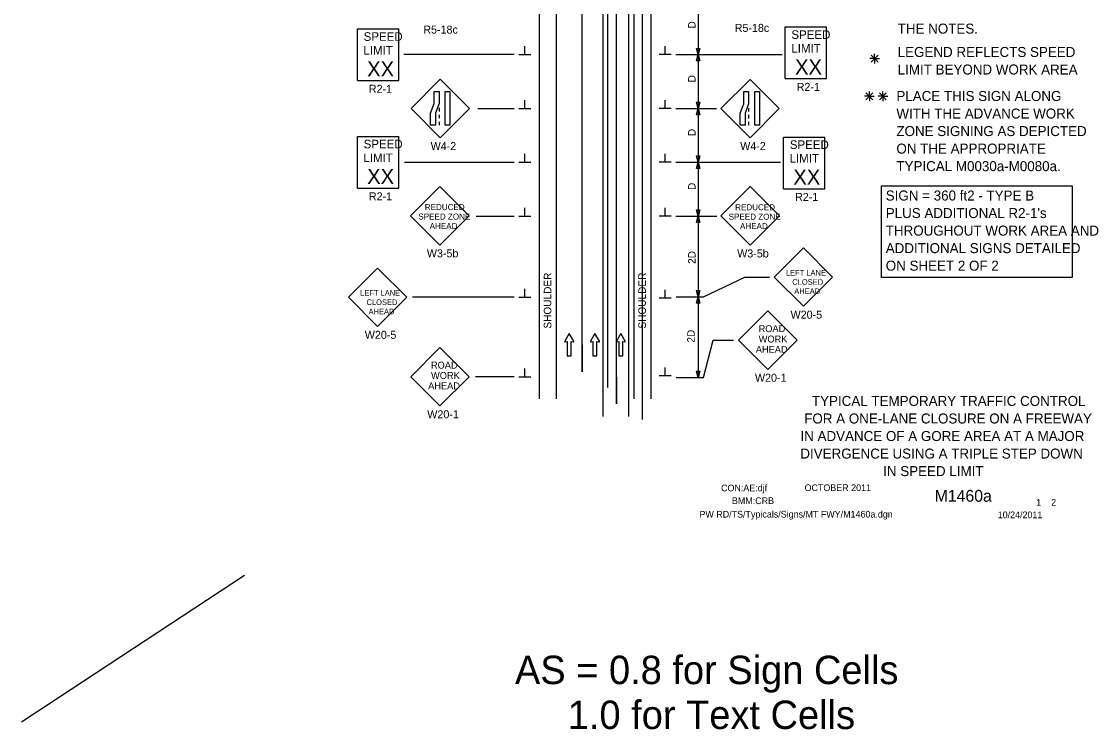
# Model space of a CAD drawing. Extents: x 16440 to 18464, y 5737 to 6974.
# Drawn here: x 16440 to 17442, y 5737 to 6395 of the extents above; entities that cross this region are included whole.
import ezdxf

# ---------------------------------------------------------------- set-up
doc = ezdxf.new("R2010")
doc.units = 0
for name, color, linetype in [('ALI_LEGAL_EX', 7, 'Continuous'), ('BORDER', 7, 'Continuous'), ('BORDER_SIGNAL_WO', 7, 'Continuous'), ('MT_SCRATCH_LEVEL_E', 7, 'Continuous'), ('PAVT_EDGE_EX', 7, 'Continuous'), ('TRAFFIC_SIGNS_PR', 7, 'Continuous'), ('TYPICAL_TEXT_DIMEN_EX', 7, 'Continuous'), ('TYPICAL_TEXT_DIMEN_PR', 7, 'Continuous')]:
    doc.layers.add(name, color=color, linetype=linetype)

msp = doc.modelspace()

# ---------------------------------------------------------------- linework, layer by layer
at = {"layer": 'ALI_LEGAL_EX'}
for p, q in [((16980.7, 6974.1), (16980.7, 6156)), ((17004.7, 6974.1), (17004.7, 6156)), ((16980.7, 6891.5), (16980.7, 6027.6)), ((17004.7, 6891.5), (17004.7, 6027.6)), ((16961.5, 6069.2), (16961.5, 6569.5)), ((16985.5, 6054.7), (16985.5, 6555)), ((16993.6, 6039.3), (16993.6, 6539.6)), ((17017.6, 6024.8), (17017.6, 6525.1))]:
    msp.add_line(p, q, dxfattribs=at)
for points in [[(16961.5, 6369.2), (16961.5, 6394.2)], [(16985.5, 6369.2), (16985.5, 6394.2)], [(16961.5, 6269.2), (16961.5, 6294.2)], [(16985.5, 6269.2), (16985.5, 6294.2)], [(16961.5, 6169.2), (16961.5, 6194.2)], [(16985.5, 6169.2), (16985.5, 6194.2)], [(16961.5, 6094.2), (16961.5, 6069.2)], [(16961.5, 6069.2), (16961.5, 6094.2)], [(16985.5, 6069.2), (16985.5, 6094.2)], [(16993.6, 6064.3), (16993.6, 6039.3)]]:
    msp.add_lwpolyline(points, dxfattribs=at)
at = {"layer": 'MT_SCRATCH_LEVEL_E'}
for p, q in [((16949.5, 6104.8), (16945.4, 6097.6)), ((16945.9, 6096.9), (16947.7, 6097.2)), ((16947.7, 6097.2), (16947.7, 6083.9)), ((16953.7, 6097.6), (16949.5, 6104.8)), ((16951.4, 6083.9), (16951.4, 6097.2)), ((16951.4, 6097.2), (16953.2, 6096.9)), ((16973.4, 6104.8), (16969.3, 6097.6)), ((16969.8, 6096.9), (16971.6, 6097.2)), ((16971.6, 6097.2), (16971.6, 6083.9)), ((16977.6, 6097.6), (16973.4, 6104.8)), ((16975.3, 6083.9), (16975.3, 6097.2)), ((16975.3, 6097.2), (16977.1, 6096.9)), ((16997.5, 6104.8), (16993.4, 6097.6)), ((16993.9, 6096.9), (16995.6, 6097.2)), ((16995.6, 6097.2), (16995.6, 6083.9)), ((17001.6, 6097.6), (16997.5, 6104.8)), ((16999.4, 6083.9), (16999.4, 6097.2)), ((16999.4, 6097.2), (17001.2, 6096.9)), ((16947.7, 6083.9), (16951.4, 6083.9)), ((16971.6, 6083.9), (16975.3, 6083.9)), ((16995.6, 6083.9), (16999.4, 6083.9))]:
    msp.add_line(p, q, dxfattribs=at)
for centre, start, end in [((16945.8, 6097.3), 150.4248, 279.9638), ((16953.3, 6097.3), 260.0362, 29.7731), ((16969.7, 6097.3), 150.4248, 279.9638), ((16977.2, 6097.3), 260.0362, 29.7731), ((16993.8, 6097.3), 150.4248, 279.9638), ((17001.2, 6097.3), 260.0362, 29.7731)]:
    msp.add_arc(centre, 0.463, start, end, dxfattribs=at)
at = {"layer": 'PAVT_EDGE_EX'}
for p, q in [((16921.5, 6569.5), (16921.5, 6043.9)), ((16937.5, 6569.5), (16937.5, 6043.9)), ((17009.5, 6569.5), (17009.5, 6043.9)), ((17025.5, 6569.5), (17025.5, 6043.9))]:
    msp.add_line(p, q, dxfattribs=at)
at = {"layer": 'TRAFFIC_SIGNS_PR'}
for p, q in [((16752.6, 6387.9), (16791, 6387.9)), ((16752.6, 6339.9), (16752.6, 6387.9)), ((16791, 6339.9), (16791, 6387.9)), ((17150.4, 6389.7), (17188.8, 6389.7)), ((17150.4, 6341.7), (17150.4, 6389.7)), ((17188.8, 6341.7), (17188.8, 6389.7)), ((16752.6, 6339.9), (16791, 6339.9)), ((16829.7, 6341), (16802.6, 6313.8)), ((16856.9, 6313.8), (16829.7, 6341)), ((17117.6, 6340.9), (17090.4, 6313.8)), ((17144.7, 6313.8), (17117.6, 6340.9)), ((17150.4, 6341.7), (17188.8, 6341.7)), ((16802.6, 6313.8), (16829.7, 6286.6)), ((16828.5, 6314.3), (16828.5, 6311.1)), ((16828.5, 6307.9), (16828.5, 6304.7)), ((16829.7, 6286.6), (16856.9, 6313.8)), ((17090.4, 6313.8), (17117.6, 6286.6)), ((17116.3, 6314.2), (17116.3, 6311)), ((17116.3, 6307.8), (17116.3, 6304.6)), ((17117.6, 6286.6), (17144.7, 6313.8)), ((16828.5, 6301.5), (16828.5, 6298.3)), ((17116.3, 6301.4), (17116.3, 6298.2)), ((16752.6, 6287.9), (16791, 6287.9)), ((16752.6, 6239.9), (16752.6, 6287.9)), ((16791, 6239.9), (16791, 6287.9)), ((17148.8, 6287.3), (17187.2, 6287.3)), ((17148.8, 6239.3), (17148.8, 6287.3)), ((17187.2, 6239.3), (17187.2, 6287.3)), ((16752.6, 6239.9), (16791, 6239.9)), ((16829.2, 6241.2), (16802.1, 6214.1)), ((16856.4, 6214.1), (16829.2, 6241.2)), ((17117.7, 6241.2), (17090.6, 6214)), ((17144.9, 6214), (17117.7, 6241.2)), ((17148.8, 6239.3), (17187.2, 6239.3)), ((16802.1, 6214.1), (16829.2, 6186.9)), ((16829.2, 6186.9), (16856.4, 6214.1)), ((17090.6, 6214), (17117.7, 6186.8)), ((17117.7, 6186.8), (17144.9, 6214)), ((17167.2, 6184.4), (17140, 6157.2)), ((17194.4, 6157.2), (17167.2, 6184.4)), ((16771.4, 6165.6), (16744.2, 6138.4)), ((16798.6, 6138.4), (16771.4, 6165.6)), ((17140, 6157.2), (17167.2, 6130)), ((17167.2, 6130), (17194.4, 6157.2)), ((16744.2, 6138.4), (16771.4, 6111.2)), ((16771.4, 6111.2), (16798.6, 6138.4)), ((17134.1, 6125.7), (17106.9, 6098.5)), ((17161.3, 6098.5), (17134.1, 6125.7)), ((17106.9, 6098.5), (17134.1, 6071.3)), ((17134.1, 6071.3), (17161.3, 6098.5)), ((16829.4, 6091.8), (16802.3, 6064.6)), ((16856.6, 6064.6), (16829.4, 6091.8)), ((16802.3, 6064.6), (16829.4, 6037.4)), ((16829.4, 6037.4), (16856.6, 6064.6))]:
    msp.add_line(p, q, dxfattribs=at)
for points in [[(16828.5, 6329.5), (16828.5, 6318.4), (16825.1, 6309.5), (16825.1, 6298.3), (16820.6, 6298.3), (16820.6, 6309.5), (16824, 6318.4), (16824, 6329.5)], [(16838.6, 6329.5), (16838.6, 6298.3), (16834.1, 6298.3), (16834.1, 6329.5)], [(17116.3, 6329.5), (17116.3, 6318.3), (17113, 6309.4), (17113, 6298.2), (17108.5, 6298.2), (17108.5, 6309.4), (17111.8, 6318.3), (17111.8, 6329.5)], [(17126.5, 6329.5), (17126.5, 6298.2), (17122, 6298.2), (17122, 6329.5)]]:
    msp.add_lwpolyline(points, close=True, dxfattribs=at)
at = {"layer": 'TYPICAL_TEXT_DIMEN_EX'}
msp.add_lwpolyline([(17239.8, 6242.1), (17417.1, 6242.1), (17417.1, 6156.8), (17239.8, 6156.8)], close=True, dxfattribs=at)
at = {"layer": 'TYPICAL_TEXT_DIMEN_PR'}
for p, q in [((17069.5, 6413.9), (17069.5, 6363.9)), ((16908.4, 6363.9), (16908.4, 6371.6)), ((17038.6, 6363.9), (17038.6, 6371.6)), ((17069.5, 6363.9), (17067.9, 6369.7)), ((17067.9, 6369.7), (17069.5, 6369.7)), ((17069.5, 6369.7), (17071.1, 6369.7)), ((17071.1, 6369.7), (17069.5, 6363.9)), ((16898.5, 6363.9), (16795.7, 6363.9)), ((16902.8, 6363.9), (16914, 6363.9)), ((17044.3, 6363.9), (17033, 6363.9)), ((17048.5, 6363.9), (17147.5, 6363.9)), ((17067.9, 6358), (17069.5, 6363.9)), ((17069.5, 6358), (17067.9, 6358)), ((17069.5, 6363.9), (17069.5, 6313.9)), ((17069.5, 6363.9), (17071.1, 6358)), ((17071.1, 6358), (17069.5, 6358)), ((17233.4, 6360.2), (17228.9, 6360.2)), ((17230.3, 6363.4), (17236.6, 6357)), ((17236.6, 6363.4), (17230.3, 6357)), ((17233.4, 6360.2), (17233.4, 6364.7)), ((17233.4, 6360.2), (17236.6, 6360.2)), ((17233.4, 6360.2), (17237.9, 6360.2)), ((17233.4, 6360.2), (17233.4, 6355.7)), ((17225.4, 6328.3), (17231.8, 6322)), ((17231.8, 6328.3), (17225.4, 6322)), ((17228.6, 6325.2), (17228.6, 6329.6)), ((17238, 6328.3), (17244.3, 6322)), ((17244.3, 6328.3), (17238, 6322)), ((17241.1, 6325.2), (17241.1, 6329.6)), ((16908.4, 6313.9), (16908.4, 6321.6)), ((17038.6, 6313.9), (17038.6, 6321.6)), ((17069.5, 6313.9), (17067.9, 6319.7)), ((17067.9, 6319.7), (17069.5, 6319.7)), ((17069.5, 6319.7), (17071.1, 6319.7)), ((17071.1, 6319.7), (17069.5, 6313.9)), ((17228.6, 6325.2), (17224.1, 6325.2)), ((17228.6, 6325.2), (17231.8, 6325.2)), ((17228.6, 6325.2), (17233.1, 6325.2)), ((17228.6, 6325.2), (17228.6, 6320.7)), ((17241.1, 6325.2), (17236.6, 6325.2)), ((17241.1, 6325.2), (17244.3, 6325.2)), ((17241.1, 6325.2), (17245.6, 6325.2)), ((17241.1, 6325.2), (17241.1, 6320.7)), ((16864.6, 6313.9), (16898.5, 6313.9)), ((16902.8, 6313.9), (16914, 6313.9)), ((17044.3, 6313.9), (17033, 6313.9)), ((17048.5, 6313.9), (17086.6, 6313.9)), ((17067.9, 6308), (17069.5, 6313.9)), ((17069.5, 6308), (17067.9, 6308)), ((17069.5, 6313.9), (17069.5, 6263.9)), ((17069.5, 6313.9), (17071.1, 6308)), ((17071.1, 6308), (17069.5, 6308)), ((16908.4, 6263.9), (16908.4, 6271.6)), ((17038.6, 6263.9), (17038.6, 6271.6)), ((17069.5, 6263.9), (17067.9, 6269.7)), ((17067.9, 6269.7), (17069.5, 6269.7)), ((17069.5, 6269.7), (17071.1, 6269.7)), ((17071.1, 6269.7), (17069.5, 6263.9)), ((16796.3, 6263.9), (16898.5, 6263.9)), ((16902.8, 6263.9), (16914, 6263.9)), ((17044.3, 6263.9), (17033, 6263.9)), ((17048.5, 6263.9), (17145.8, 6263.9)), ((17067.9, 6258), (17069.5, 6263.9)), ((17069.5, 6258), (17067.9, 6258)), ((17069.5, 6263.9), (17069.5, 6213.9)), ((17069.5, 6263.9), (17071.1, 6258)), ((17071.1, 6258), (17069.5, 6258)), ((16908.4, 6213.9), (16908.4, 6221.6)), ((17038.6, 6213.9), (17038.6, 6221.6)), ((17069.5, 6213.9), (17067.9, 6219.7)), ((17067.9, 6219.7), (17069.5, 6219.7)), ((17069.5, 6219.7), (17071.1, 6219.7)), ((17071.1, 6219.7), (17069.5, 6213.9)), ((16862.9, 6213.9), (16898.5, 6213.9)), ((16902.8, 6213.9), (16914, 6213.9)), ((17044.3, 6213.9), (17033, 6213.9)), ((17048.5, 6213.9), (17086.7, 6213.9)), ((17067.9, 6208), (17069.5, 6213.9)), ((17069.5, 6208), (17067.9, 6208)), ((17069.5, 6213.9), (17069.5, 6138.9)), ((17069.5, 6213.9), (17071.1, 6208)), ((17071.1, 6208), (17069.5, 6208)), ((17074.5, 6138.9), (17112.7, 6157.2)), ((17112.7, 6157.2), (17135.6, 6157.2)), ((16898.5, 6138.4), (16804, 6138.4)), ((16902.8, 6138.4), (16914, 6138.4)), ((16908.4, 6138.4), (16908.4, 6146.2)), ((17044.3, 6137.6), (17033, 6137.6)), ((17038.6, 6137.6), (17038.6, 6145.4)), ((17049, 6138.9), (17074.5, 6138.9)), ((17069.5, 6138.9), (17067.9, 6144.7)), ((17067.9, 6144.7), (17069.5, 6144.7)), ((17067.9, 6133), (17069.5, 6138.9)), ((17069.5, 6144.7), (17071.1, 6144.7)), ((17071.1, 6144.7), (17069.5, 6138.9)), ((17069.5, 6138.9), (17069.5, 6063.9)), ((17069.5, 6138.9), (17071.1, 6133)), ((17069.5, 6133), (17067.9, 6133)), ((17071.1, 6133), (17069.5, 6133)), ((17074.5, 6063.9), (17083.5, 6098.4)), ((17083.5, 6098.4), (17102.3, 6098.4)), ((16908.4, 6064.5), (16908.4, 6072.3)), ((17038.6, 6065.3), (17038.6, 6073)), ((17069.5, 6063.9), (17067.9, 6069.7)), ((17067.9, 6069.7), (17069.5, 6069.7)), ((17069.5, 6069.7), (17071.1, 6069.7)), ((17071.1, 6069.7), (17069.5, 6063.9)), ((16898.5, 6064.5), (16862.5, 6064.5)), ((16902.8, 6064.5), (16914, 6064.5)), ((17044.3, 6065.3), (17033, 6065.3)), ((17049, 6063.9), (17074.5, 6063.9)), ((16647.8, 5880), (16440.4, 5743.5))]:
    msp.add_line(p, q, dxfattribs=at)

# ---------------------------------------------------------------- texts
at = {"layer": 'BORDER'}
for s, p in [('TYPICAL TEMPORARY TRAFFIC CONTROL', (17175.2, 6037.4)), ('FOR A ONE-LANE CLOSURE ON A FREEWAY', (17168, 6021.1)), ('IN ADVANCE OF A GORE AREA AT A MAJOR', (17164.5, 6004.8)), ('DIVERGENCE USING A TRIPLE STEP DOWN ', (17164.4, 5988.5)), ('IN SPEED LIMIT', (17241.4, 5972.2))]:
    msp.add_text(s, height=9.3, dxfattribs=at).set_placement(p)
at = {"layer": 'BORDER_SIGNAL_WO'}
for s, height, p in [('CON:AE:djf  ', 6.2, (17090.7, 5958.1)), ('    OCTOBER 2011    ', 6.2, (17159.1, 5958.3)), ('    M1460a   ', 11, (17272.9, 5948.4)), ('BMM:CRB', 6.2, (17100.8, 5946.2)), (' 1    2 ', 6.2, (17381.4, 5944.7)), ('PW RD/TS/Typicals/Signs/MT FWY/M1460a.dgn      ', 6.2, (17070.6, 5933.7)), ('10/24/2011    ', 6.2, (17347.9, 5933.1)), ('AS = 0.8 for Sign Cells', 26.424, (16899.1, 5778.9)), ('     1.0 for Text Cells', 26.424, (16899.1, 5737.2))]:
    msp.add_text(s, height=height, dxfattribs=at).set_placement(p)
at = {"layer": 'TRAFFIC_SIGNS_PR'}
for s, height, p in [('R5-18c', 7.44, (16813.9, 6383.4)), ('R5-18c', 7.44, (17103.4, 6385)), ('SPEED', 8, (16758.4, 6376.7)), ('SPEED', 8, (17156.1, 6378.5)), ('LIMIT', 8, (16758.2, 6363.9)), ('LIMIT', 8, (17156, 6365.7)), ('XX', 14.03, (16761.7, 6343.6)), ('XX', 14.03, (17159.5, 6345.4)), ('R2-1', 7.44, (17161, 6330.2)), ('R2-1', 7.44, (16763.3, 6328.4)), ('SPEED', 8, (16758.4, 6276.8)), ('W4-2', 7.44, (16820.7, 6275.2)), ('W4-2', 7.44, (17108.5, 6275.2)), ('SPEED', 8, (17154.6, 6276.2)), ('LIMIT', 8, (16758.2, 6264)), ('LIMIT', 8, (17154.4, 6263.4)), ('XX', 14.03, (16761.7, 6243.7)), ('XX', 14.03, (17157.9, 6243.1)), ('R2-1', 7.44, (16763.3, 6228.5)), ('R2-1', 7.44, (17159.5, 6227.9)), ('REDUCED', 5.6, (16815.3, 6219.4)), ('REDUCED', 5.6, (17103.8, 6219.3)), ('SPEED ZONE', 5.6, (16809.3, 6210.6)), ('AHEAD', 5.6, (16819.8, 6201.8)), ('SPEED ZONE', 5.6, (17097.8, 6210.5)), ('AHEAD', 5.6, (17108.3, 6201.7)), ('W3-5b', 7.44, (16817.2, 6175.5)), ('W3-5b', 7.44, (17105.7, 6175.4)), ('LEFT LANE', 5.21, (17151, 6158.6)), ('CLOSED', 5.21, (17156.9, 6150)), ('LEFT LANE', 5.21, (16755.2, 6139.8)), ('AHEAD', 5.21, (17158.8, 6141.4)), ('CLOSED', 5.21, (16761.1, 6131.2)), ('AHEAD', 5.21, (16763, 6122.6)), ('W20-5', 7.45, (17155.3, 6118.5)), ('W20-5', 7.45, (16759.5, 6099.8)), ('ROAD', 6.41, (17125.6, 6106)), ('WORK', 6.41, (17125.7, 6096.4)), ('AHEAD', 6.41, (17123, 6086.8)), ('ROAD', 6.41, (16821, 6072.1)), ('WORK', 6.41, (16821.1, 6062.5)), ('W20-1', 7.45, (17122.2, 6059.9)), ('AHEAD', 6.41, (16818.4, 6052.9)), ('W20-1', 7.45, (16817.6, 6025.9))]:
    msp.add_text(s, height=height, dxfattribs=at).set_placement(p)
at = {"layer": 'TYPICAL_TEXT_DIMEN_EX'}
for s, p in [('THE NOTES.', (17254.9, 6383.4)), ('LEGEND REFLECTS SPEED', (17254.9, 6361.7)), ('LIMIT BEYOND WORK AREA', (17254.9, 6345.4)), ('PLACE THIS SIGN ALONG', (17253.7, 6320.8)), ('WITH THE ADVANCE WORK', (17253.7, 6304.5)), ('ZONE SIGNING AS DEPICTED', (17253.7, 6288.2)), ('ON THE APPROPRIATE', (17253.7, 6271.9)), ('TYPICAL M0030a-M0080a.', (17253.7, 6255.6)), ('SIGN = 360 ft2 - TYPE B', (17243.8, 6228.3)), ("PLUS ADDITIONAL R2-1's", (17243.8, 6212)), ('THROUGHOUT WORK AREA AND', (17243.8, 6195.7)), ('ADDITIONAL SIGNS DETAILED', (17243.8, 6179.4)), ('ON SHEET 2 OF 2', (17243.8, 6163.1))]:
    msp.add_text(s, height=9.3, dxfattribs=at).set_placement(p)
at = {"layer": 'TYPICAL_TEXT_DIMEN_PR'}
for s, p in [('D', (17067, 6388.1)), ('D', (17067, 6338.1)), ('D', (17067, 6288.1)), ('D', (17067, 6238.1)), ('2D', (17067, 6169.4)), ('SHOULDER', (16932.9, 6109.3)), ('SHOULDER', (17020.8, 6109.3)), ('2D', (17066.2, 6096.3))]:
    msp.add_text(s, height=7, rotation=90, dxfattribs=at).set_placement(p)

doc.saveas('drawing.dxf')
